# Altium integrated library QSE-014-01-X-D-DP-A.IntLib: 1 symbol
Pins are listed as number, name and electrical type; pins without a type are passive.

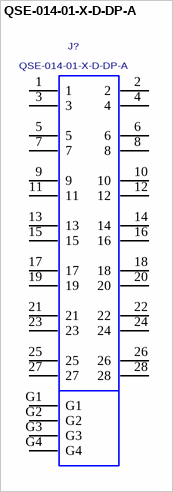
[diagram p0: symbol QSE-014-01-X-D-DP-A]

## QSE-014-01-X-D-DP-A
designator J?
HIGH SPEED SOCKET STRIP, DIFFERENTIAL, .8mm PITCH, 28 PINS; MANUFACTURER: SAMTEC, INC
footprint QSE-014-01-X-D-DP-A
pins: 1, 2, 3, 4, 5, 6, 7, 8, 9, 10, 11, 12, 13, 14, 15, 16, 17, 18, 19, 20, 21, 22, 23, 24, 25, 26, 27, 28, G1, G2, G3, G4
